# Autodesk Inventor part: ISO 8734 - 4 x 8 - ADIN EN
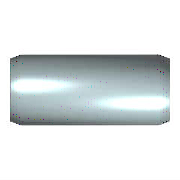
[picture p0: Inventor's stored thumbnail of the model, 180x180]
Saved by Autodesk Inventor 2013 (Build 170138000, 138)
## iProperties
IsCustomPart: 1
Created: 2012-02
Part Number: ISO 8734 - 4 x 8 - ADIN EN
Material: Stahl
Description: Zylinderstift
Document SubType Name: Modeling
Standard: ISO 8734
Designer: rYan
Standards Organization: DIN
Language: de-DE
Size Designation: 4 x 10 - A
Categories: <MemberInstance><Categories><Category DisplayName="Verbindungselemente" InternalName="e4da775c-781d-43d5-af7c-5136215cf5a6" Mnemonic="FSTN"><Category DisplayNam
Density: 7.85 g/cm^3
Mass: 0.778972 g
Surface Area: 1.21467 cm^2
Volume: 0.0992321 cm^3
Author: rYan
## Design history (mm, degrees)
sketch "Skizze"
  geometry: C1 r 2 at (0, 0); 1 further point
  constraints: 1 centre point, 1 coincident
  dimensions: "d1" = 4 diameter of C1 (= NND)
extrude "Körper" new body sketch "Skizze" distance "d2" = 8 (= NLG); taper "d3" = 0 deg
body "Solid1"
chamfer "Fase1" distance "d4" = 0.63 (= PHH); stored, may be unused: angle "d5" = 15 deg (= FAWI), second distance "d11" = 0.63 (= PHH)
chamfer "Fase2" distance "d8" = 0.63 (= PHH); stored, may be unused: angle "d9" = 15 deg (= FAWI), second distance "d12" = 0.63 (= PHH)
other parameters: "NND" = 4 [user parameter; used in 1 equation term], "NLG" = 8 [user parameter; used in 1 equation term], "PHH" = 0.63 [user parameter; used in 5 equation terms], "FAWI" = 15 deg [user parameter; used in 2 equation terms], "d13" = 0, "d15" = 0, "d16" = 0, "PHH2" = 0.63 (= PHH) [user parameter], "FAWI2" = 15 deg [user parameter]
